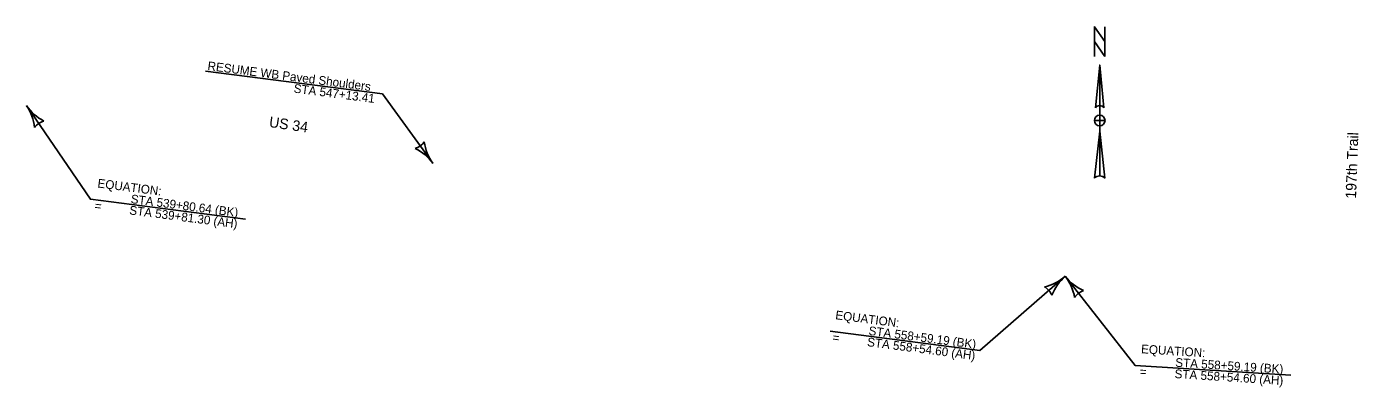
# Model space of a CAD drawing. Extents: x 22712865 to 22760106, y 6235088 to 6238602.
# Drawn here: x 22731634 to 22734010, y 6235567 to 6236210 of the extents above; entities that cross this region are included whole.
import ezdxf

# ---------------------------------------------------------------- set-up
doc = ezdxf.new("R2010")
doc.units = 0
for name, color, linetype in [('Contours Major', 7, 'Continuous'), ('Default', 7, 'Continuous'), ('Draft_3', 7, 'Continuous'), ('dsnTextOdd', 7, 'Continuous'), ('Entrance', 7, 'Continuous')]:
    doc.layers.add(name, color=color, linetype=linetype)

msp = doc.modelspace()

# ---------------------------------------------------------------- linework, layer by layer
at = {"layer": 'Contours Major'}
msp.add_lwpolyline([(22731633.7, 6236068.7), (22731747.6, 6235901.9), (22732024.3, 6235866.1)], dxfattribs=at)
for centre, radius, start, end in [((22731563.5, 6236020.7), 85, 6.2589, 34.3314), ((22731703.9, 6236116.6), 85, 214.3314, 242.4039), ((22731673.9, 6236009.8), 32.8, 106.5981, 142.0648)]:
    msp.add_arc(centre, radius, start, end, dxfattribs=at)
at = {"layer": 'Draft_3'}
msp.add_lwpolyline([(22732358.7, 6235965.9), (22732268.5, 6236089.6), (22731952.6, 6236130.4)], dxfattribs=at)
for centre, radius, start, end in [((22732316.8, 6236023.5), 32.8, 288.356, 323.8227), ((22732427.4, 6236015.9), 85, 188.0168, 216.0893), ((22732290.1, 6235915.8), 85, 36.0893, 64.1618)]:
    msp.add_arc(centre, radius, start, end, dxfattribs=at)
at = {"layer": 'dsnTextOdd'}
for p, q in [((22733548.3, 6236141.1), (22733555.9, 6236065)), ((22733548.3, 6236141.1), (22733548.3, 6235943.3)), ((22733540.7, 6236065), (22733540.7, 6236065)), ((22733541, 6236065.7), (22733542.4, 6236067.3)), ((22733538.8, 6235939.5), (22733548.3, 6236023.2)), ((22733548.3, 6236032.7), (22733548.3, 6236032.7))]:
    msp.add_line(p, q, dxfattribs=at)
msp.add_lwpolyline([(22733557.8, 6236156.3), (22733538.8, 6236182.9), (22733538.8, 6236209.5), (22733557.8, 6236182.9)], close=True, dxfattribs=at)
for points in [[(22733538.8, 6236156.3), (22733538.8, 6236209.5), (22733557.8, 6236182.9), (22733557.8, 6236209.5)], [(22733540.7, 6236065), (22733548.3, 6236141.1), (22733548.3, 6236068.8)], [(22733557.8, 6236042.2), (22733548.3, 6236042.2), (22733548.3, 6236051.7)], [(22733548.3, 6236032.7), (22733548.3, 6236042.2), (22733538.8, 6236042.2)], [(22733548.3, 6235943.3), (22733548.3, 6236023.2), (22733557.8, 6235939.5)], [(22733486.8, 6235764.5), (22733334.2, 6235632.1), (22733067.4, 6235666.5)]]:
    msp.add_lwpolyline(points, dxfattribs=at)
for centre, radius, start, end in [((22733548.3, 6236059.3), 9.51, 90.0204, 143.1257), ((22733548.3, 6236059.3), 9.5, 36.8481, 90.0218), ((22733548.3, 6236042.2), 9.51, 90, 180), ((22733548.3, 6236042.2), 9.51, 0, 90), ((22733548.3, 6236042.2), 9.51, 180, 270), ((22733548.3, 6236042.2), 9.51, 270, 360), ((22733548.3, 6235929.5), 13.8, 89.9894, 133.619), ((22733548.3, 6235929.5), 13.8, 46.4021, 90.0006), ((22733431.1, 6235828.7), 85, 282.8812, 310.9537), ((22733542.5, 6235700.3), 85, 130.9537, 159.0262), ((22733433, 6235717.8), 32.8, 23.2204, 58.6871)]:
    msp.add_arc(centre, radius, start, end, dxfattribs=at)
at = {"layer": 'Entrance'}
msp.add_lwpolyline([(22733486.8, 6235764.5), (22733611.4, 6235605.5), (22733889.1, 6235588)], dxfattribs=at)
for centre, radius, start, end in [((22733419.9, 6235712.1), 85, 10.0059, 38.0783), ((22733553.7, 6235816.9), 85, 218.0783, 246.1508), ((22733530.8, 6235708.4), 32.8, 110.345, 145.8117)]:
    msp.add_arc(centre, radius, start, end, dxfattribs=at)

# ---------------------------------------------------------------- texts
at = {"layer": 'Contours Major'}
for s, height, p in [('EQUATION:', 15.6, (22731759.5, 6235923)), ('STA 539+80.64 (BK)', 15.601, (22731818.8, 6235895)), ('=', 15.6, (22731754.3, 6235882.9)), ('STA 539+81.30 (AH)', 15.601, (22731816.2, 6235875))]:
    msp.add_text(s, height=height, rotation=352.6426, dxfattribs=at).set_placement(p)
at = {"layer": 'Default'}
for s, rotation, p in [('US 34', 351.6578, (22732065.4, 6236030.8)), ('197th Trail', 87.947, (22734005.7, 6235902.6))]:
    msp.add_text(s, height=18.75, rotation=rotation, dxfattribs=at).set_placement(p)
at = {"layer": 'Draft_3'}
for s, p in [('RESUME WB Paved Shoulders', (22731955.8, 6236132.3)), ('STA 547+13.41', (22732109.5, 6236092.1))]:
    msp.add_text(s, height=15.601, rotation=352.6426, dxfattribs=at).set_placement(p)
at = {"layer": 'dsnTextOdd'}
for s, height, p in [('EQUATION:', 15.6, (22733076, 6235688.1)), ('STA 558+59.19 (BK)', 15.601, (22733135.3, 6235660.1)), ('=', 15.6, (22733070.8, 6235648.1)), ('STA 558+54.60 (AH)', 15.601, (22733132.7, 6235640.1))]:
    msp.add_text(s, height=height, rotation=352.6426, dxfattribs=at).set_placement(p)
at = {"layer": 'Entrance'}
for s, height, p in [('EQUATION:', 15.6, (22733621.8, 6235627.4)), ('STA 558+59.19 (BK)', 15.601, (22733682.8, 6235603.3)), ('=', 15.6, (22733619.3, 6235587)), ('STA 558+54.60 (AH)', 15.601, (22733681.6, 6235583.1))]:
    msp.add_text(s, height=height, rotation=356.3895, dxfattribs=at).set_placement(p)

doc.saveas('drawing.dxf')
